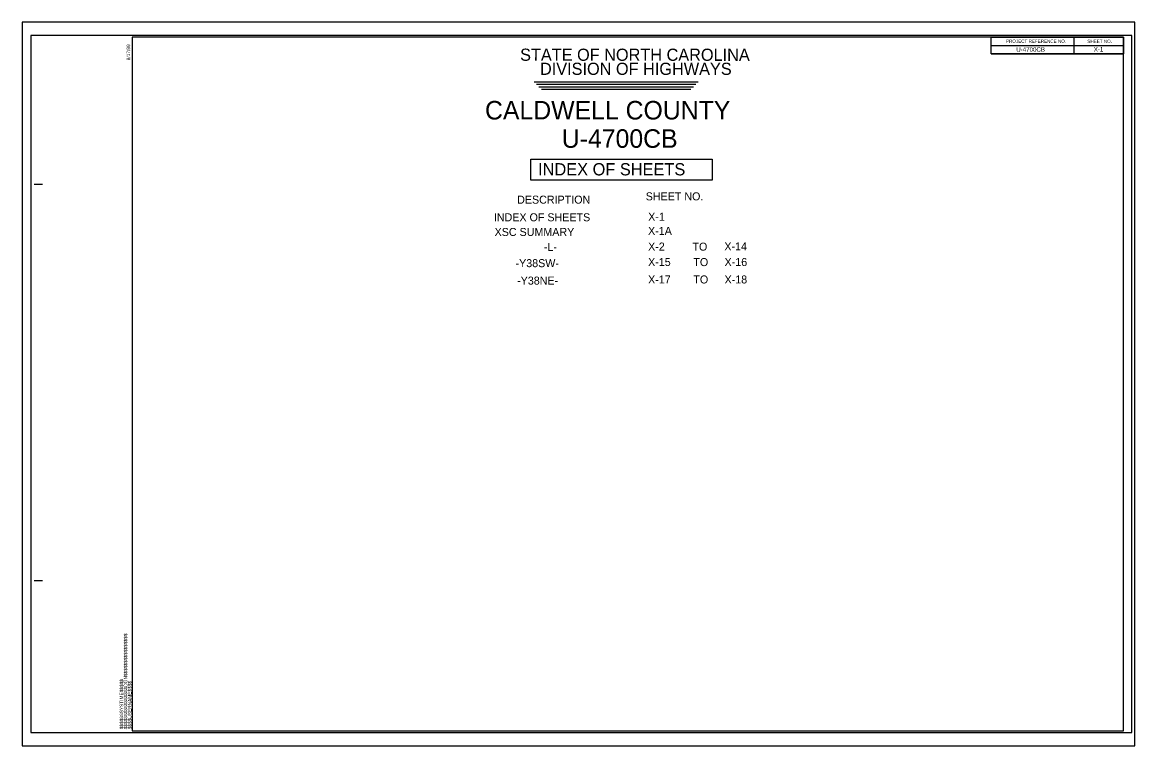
# Model space of a CAD drawing. Extents: x 2221 to 2389, y -3371 to -3261.
import ezdxf

# ---------------------------------------------------------------- set-up
doc = ezdxf.new("R2010")
doc.units = 0
for name, color, linetype in [('Default', 7, 'Continuous'), ('Old_Level_12', 7, 'Continuous'), ('Old_Level_40', 7, 'Continuous'), ('Old_Level_44', 7, 'Continuous'), ('Sheet Block Title CELL', 7, 'Continuous'), ('Sheet Data Field CELL', 7, 'Continuous'), ('Sheet Plan CELL', 7, 'Continuous'), ('Sheet Plot Border Inside CELL', 7, 'Continuous'), ('Sheet Plot Border Outside CELL', 7, 'Continuous')]:
    doc.layers.add(name, color=color, linetype=linetype)

msp = doc.modelspace()

# ---------------------------------------------------------------- linework, layer by layer
at = {"layer": 'Default'}
msp.add_lwpolyline([(2297.67, -3282.01), (2325.14, -3282.01), (2325.14, -3285.21), (2297.67, -3285.21)], close=True, dxfattribs=at)
at = {"layer": 'Old_Level_12'}
for p, q in [((2298.2, -3270.29), (2323.04, -3270.3)), ((2298.2, -3270.3), (2323.04, -3270.3)), ((2298.55, -3270.68), (2322.65, -3270.68)), ((2298.93, -3271.05), (2322.29, -3271.05)), ((2299.3, -3271.42), (2321.9, -3271.42))]:
    msp.add_line(p, q, dxfattribs=at)
at = {"layer": 'Sheet Block Title CELL'}
for p, q in [((2379.88, -3263.55), (2379.88, -3266.05)), ((2367.38, -3264.8), (2387.38, -3264.8)), ((2367.38, -3266.05), (2387.38, -3266.05))]:
    msp.add_line(p, q, dxfattribs=at)
msp.add_lwpolyline([(2367.38, -3263.54), (2387.38, -3263.54), (2387.38, -3266.05), (2367.38, -3266.05)], close=True, dxfattribs=at)
at = {"layer": 'Sheet Plan CELL'}
for p, q in [((2237.38, -3263.54), (2237.38, -3263.54)), ((2222.53, -3285.79), (2223.78, -3285.79)), ((2222.53, -3345.8), (2223.78, -3345.8)), ((2237.38, -3368.55), (2237.38, -3368.55))]:
    msp.add_line(p, q, dxfattribs=at)
msp.add_lwpolyline([(2387.38, -3263.54), (2237.38, -3263.54), (2237.38, -3368.55), (2387.38, -3368.55)], close=True, dxfattribs=at)
at = {"layer": 'Sheet Plot Border Inside CELL'}
msp.add_lwpolyline([(2222.03, -3368.8), (2388.63, -3368.8), (2388.63, -3263.29), (2222.03, -3263.29)], close=True, dxfattribs=at)
at = {"layer": 'Sheet Plot Border Outside CELL'}
msp.add_lwpolyline([(2220.73, -3370.8), (2389.08, -3370.8), (2389.08, -3261.29), (2220.73, -3261.29)], close=True, dxfattribs=at)

# ---------------------------------------------------------------- texts
at = {"layer": 'Default'}
for s, height, p in [('INDEX OF SHEETS', 1.8509, (2298.79, -3284.47)), ('DESCRIPTION', 1.2112, (2295.62, -3288.75)), ('SHEET NO.', 1.211, (2315.08, -3288.25))]:
    msp.add_text(s, height=height, rotation=359.992, dxfattribs=at).set_placement(p)
for s, height, p in [('INDEX OF SHEETS ', 1.2112, (2292.1, -3291.42)), ('X-1', 1.211, (2315.45, -3291.34)), ('XSC SUMMARY', 1.2112, (2292.21, -3293.64)), ('X-1A', 1.211, (2315.43, -3293.47)), ('X-2', 1.211, (2315.44, -3295.85)), ('TO', 1.211, (2322.15, -3295.86)), ('X-14', 1.211, (2326.98, -3295.82)), ('-L-', 1.211, (2299.67, -3295.92)), ('-Y38SW-', 1.211, (2295.38, -3298.36)), ('X-15', 1.211, (2315.44, -3298.19)), ('TO', 1.211, (2322.29, -3298.2)), ('X-16', 1.211, (2327.01, -3298.19)), ('X-17', 1.211, (2315.44, -3300.83)), ('TO', 1.211, (2322.29, -3300.83)), ('X-18', 1.211, (2327.01, -3300.83)), ('-Y38NE-', 1.211, (2295.62, -3301))]:
    msp.add_text(s, height=height, dxfattribs=at).set_placement(p)
at = {"layer": 'Old_Level_40'}
for s, height, p in [('CALDWELL COUNTY', 2.8069, (2290.76, -3276.01)), ('U-4700CB', 2.807, (2302.38, -3280.3))]:
    msp.add_text(s, height=height, rotation=359.9982, dxfattribs=at).set_placement(p)
at = {"layer": 'Old_Level_44'}
for s, p in [('STATE OF NORTH CAROLINA', (2296.07, -3267.13)), ('DIVISION OF HIGHWAYS', (2299.08, -3269.26))]:
    msp.add_text(s, height=1.8416, rotation=359.9915, dxfattribs=at).set_placement(p)
at = {"layer": 'Sheet Block Title CELL'}
for s, p in [('PROJECT REFERENCE NO.', (2369.6, -3264.41)), ('SHEET NO.', (2381.91, -3264.42))]:
    msp.add_text(s, height=0.5, dxfattribs=at).set_placement(p)
at = {"layer": 'Sheet Data Field CELL'}
for s, p in [('U-4700CB', (2371.15, -3265.76)), ('X-1', (2382.88, -3265.73))]:
    msp.add_text(s, height=0.675, dxfattribs=at).set_placement(p)
at = {"layer": 'Sheet Plan CELL'}
for s, p in [('8/17/99', (2237.06, -3267.06)), ('$$$$$$$$$$$$$$$$DGN$$$$$$$$$$$$$$$$', (2236.62, -3368.31)), ('$$$$$$SYSTIME$$$$$', (2236.01, -3368.31)), ('$$$$USERNAME$$$$', (2237.27, -3368.31))]:
    msp.add_text(s, height=0.525, rotation=90, dxfattribs=at).set_placement(p)

doc.saveas('drawing.dxf')
